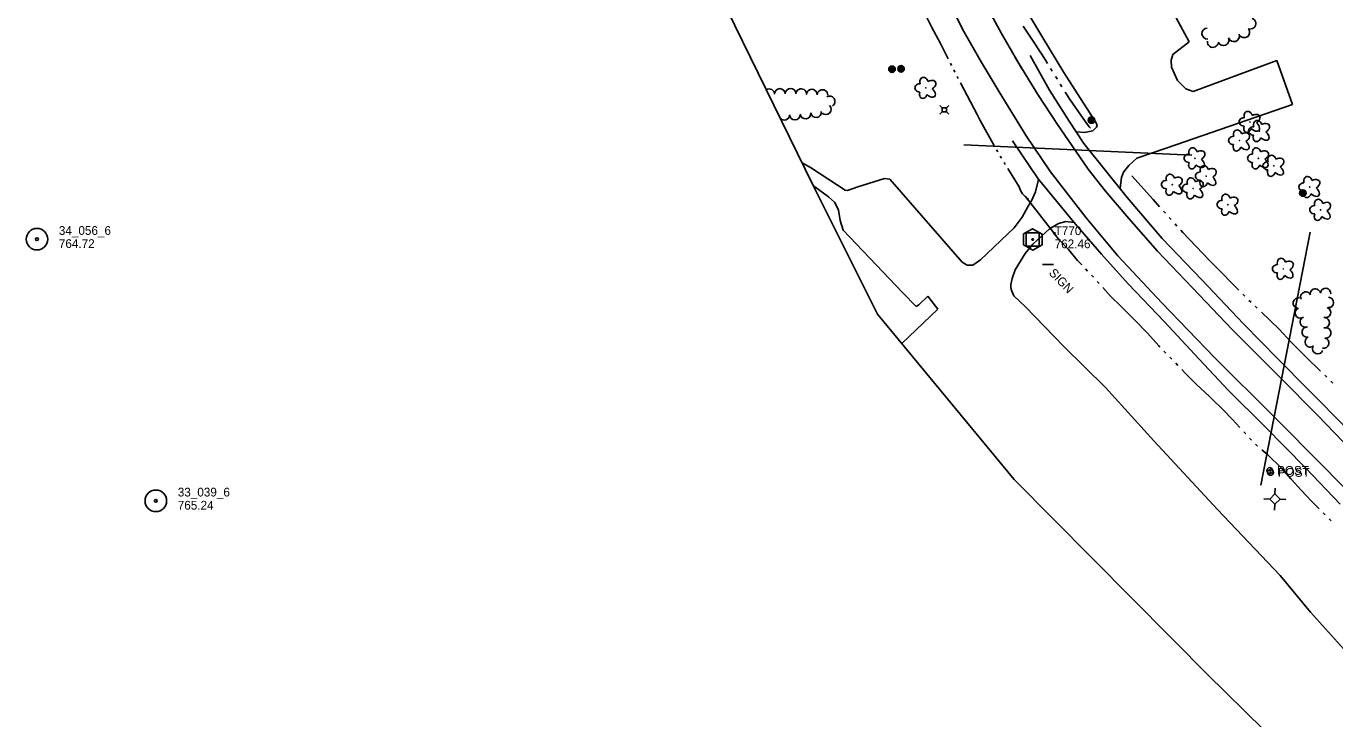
# Model space of a CAD drawing. Extents: x 589250 to 1188077, y 162953 to 363065.
# Drawn here: x 592222 to 593118, y 173959 to 174433 of the extents above; entities that cross this region are included whole.
import ezdxf

# ---------------------------------------------------------------- set-up
doc = ezdxf.new("R2010")
doc.units = 0
for name, color, linetype in [('E_DRN', 7, 'Continuous'), ('E_DRN_DrainTile', 7, 'Continuous'), ('E_DRN_Pipe', 7, 'Continuous'), ('E_DWY', 7, 'Continuous'), ('E_LAND_TreeLine_P', 7, 'Continuous'), ('E_LAND_Vegetation', 7, 'Continuous'), ('E_MAP_Control', 7, 'Continuous'), ('E_MAP_Limits', 7, 'Continuous'), ('E_MAP_PassPoints', 7, 'Continuous'), ('E_MISCPROP', 7, 'Continuous'), ('E_RDWY', 7, 'Continuous'), ('E_RDWY_Gravel', 7, 'Continuous'), ('E_SGN', 7, 'Continuous'), ('E_SGN_Text', 7, 'Continuous'), ('E_UTL_AG_Bold', 7, 'Continuous'), ('E_WTR_FlowLine', 7, 'Continuous')]:
    doc.layers.add(name, color=color, linetype=linetype)

msp = doc.modelspace()

# ---------------------------------------------------------------- linework, layer by layer
at = {"layer": 'E_DRN'}
for centre, radius, start, end in [((592906.93, 174315.61), 0.717, 258.04059, 4.3008), ((592926.09, 174290.91), 0.949, 72.43132, 178.69152)]:
    msp.add_arc(centre, radius, start, end, dxfattribs=at)
at = {"layer": 'E_DRN_DrainTile'}
for p, q in [((593019.9, 174345.12), (592863.65, 174352.13)), ((593100.87, 174292.34), (593067.07, 174118.97))]:
    msp.add_line(p, q, dxfattribs=at)
at = {"layer": 'E_DRN_Pipe'}
msp.add_line((592905.79, 174316.91), (592926.92, 174289.76), dxfattribs=at)
at = {"layer": 'E_DWY'}
for p, q in [((592900.5, 174454.33), (592917.9, 174425.3)), ((593009.02, 174439.01), (593018.06, 174422.58)), ((592917.9, 174425.3), (592932.13, 174401.76)), ((593006.8, 174414.08), (593005.6, 174410.12)), ((593018.06, 174422.58), (593006.8, 174414.08)), ((593005.6, 174410.12), (593005.9, 174405.2)), ((593005.9, 174405.2), (593009.94, 174396.11)), ((593020.86, 174388.58), (593078.1, 174409.86)), ((593078.1, 174409.86), (593088.76, 174379.64)), ((592932.13, 174401.76), (592947.76, 174377.55)), ((593009.94, 174396.11), (593015.66, 174390.5)), ((593015.66, 174390.5), (593020.86, 174388.58)), ((593088.76, 174379.64), (593002.26, 174349.93)), ((592947.76, 174377.55), (592954.41, 174367.16)), ((592941.19, 174360.99), (592940.67, 174361.07)), ((592946.23, 174360.56), (592941.19, 174360.99)), ((592951.97, 174361.7), (592946.23, 174360.56)), ((592954.46, 174364.12), (592951.97, 174361.7)), ((592954.41, 174367.16), (592955.05, 174365.45)), ((592955.05, 174365.45), (592954.46, 174364.12)), ((592982.11, 174343.07), (592976.73, 174337.84)), ((593002.26, 174349.93), (592982.11, 174343.07)), ((592758.76, 174336.56), (592753, 174339.74)), ((592782.34, 174321.11), (592758.76, 174336.56)), ((592973.08, 174333.36), (592971.64, 174329.65)), ((592976.73, 174337.84), (592973.08, 174333.36)), ((592809.48, 174329.15), (592791.21, 174323.34)), ((592812.98, 174328.65), (592809.48, 174329.15)), ((592862.49, 174271.69), (592812.98, 174328.65)), ((592914.91, 174328.38), (592912.88, 174319.84)), ((592971.15, 174326.39), (592970.65, 174322.25)), ((592971.64, 174329.65), (592971.15, 174326.39)), ((592760.75, 174323.92), (592771.02, 174316.56)), ((592771.02, 174316.56), (592775.42, 174312.69)), ((592783.96, 174320.86), (592782.34, 174321.11)), ((592791.21, 174323.34), (592783.96, 174320.86)), ((592912.88, 174319.84), (592909.97, 174313.7)), ((592775.42, 174312.69), (592777.99, 174307.43)), ((592777.99, 174307.43), (592778.97, 174300.31)), ((592907.81, 174310.07), (592903.65, 174302.51)), ((592909.97, 174313.7), (592907.81, 174310.07)), ((592778.97, 174300.31), (592781.1, 174293.66)), ((592903.65, 174302.51), (592898.08, 174295.25)), ((592928.61, 174298.22), (592922.38, 174294.55)), ((592933.61, 174299.68), (592928.61, 174298.22)), ((592939.3, 174298.83), (592933.61, 174299.68)), ((592781.1, 174293.66), (592821.69, 174251.02)), ((592898.08, 174295.25), (592875.14, 174273.42)), ((592916.79, 174289.64), (592911.04, 174284.09)), ((592922.38, 174294.55), (592916.79, 174289.64)), ((592911.04, 174284.09), (592905.62, 174277.62)), ((592866.01, 174269.57), (592862.49, 174271.69)), ((592875.14, 174273.42), (592869.78, 174269.6)), ((592905.62, 174277.62), (592898.8, 174266.54)), ((592869.78, 174269.6), (592866.01, 174269.57)), ((592898.8, 174266.54), (592896.79, 174260.55)), ((592896.79, 174260.55), (592895.9, 174256.4)), ((592895.9, 174256.4), (592895.92, 174254.11)), ((592895.92, 174254.11), (592896.63, 174251.81)), ((592821.69, 174251.02), (592830.97, 174241.44)), ((592832.8, 174242.6), (592839.16, 174248.41)), ((592839.16, 174248.41), (592845.91, 174239.5)), ((592896.63, 174251.81), (592898.04, 174248.61)), ((592898.04, 174248.61), (592905.92, 174241.09)), ((592845.91, 174239.5), (592821.16, 174216.02)), ((592830.97, 174241.44), (592832.8, 174242.6)), ((592905.92, 174241.09), (592932.12, 174213.95)), ((592932.12, 174213.95), (592960.64, 174185.92)), ((592960.64, 174185.92), (592993.88, 174149.36)), ((592993.88, 174149.36), (593037.5, 174102.38)), ((593037.5, 174102.38), (593080.41, 174056.99)), ((593101.04, 174032.06), (593080.41, 174056.99)), ((593152.12, 173975.05), (593101.04, 174032.06))]:
    msp.add_line(p, q, dxfattribs=at)
at = {"layer": 'E_LAND_TreeLine_P'}
for centre, radius, start, end in [((593030.57, 174428.33), 3.79, 92.772, 272.772), ((593059.84, 174435.23), 3.79, 249.19878, 69.19878), ((593034.25, 174422.65), 3.79, 173.44438, 353.44438), ((593041.5, 174423.89), 3.79, 201.88731, 21.88731), ((593048.6, 174426.57), 3.79, 199.34743, 19.34743), ((593055.66, 174429.28), 3.79, 215.78699, 35.78699), ((592730.5, 174386.74), 3.64, 1.65562, 123.29635), ((592737.77, 174386.95), 3.64, 1.65562, 181.65562), ((592745.05, 174387.16), 3.64, 1.65562, 181.65562), ((592752.33, 174386.86), 3.64, 357.41999, 177.41999), ((592759.6, 174386.53), 3.64, 357.41999, 177.41999), ((592766.87, 174386.2), 3.64, 357.41999, 177.41999), ((592769.2, 174376.42), 3.64, 225.48648, 45.48648), ((592771.86, 174381.86), 3.64, 303.2217, 123.2217), ((592733.49, 174372.56), 3.64, 354.12954, 0.98469), ((592740.77, 174372.69), 3.64, 180.98469, 190.41572), ((592740.77, 174372.69), 3.64, 221.76161, 0.98469), ((592748.05, 174372.81), 3.64, 180.98469, 0.98469), ((592755.29, 174373.56), 3.64, 186.96955, 6.96955), ((592762.51, 174374.45), 3.64, 186.96955, 6.96955), ((593104.38, 174249.89), 3.57, 10.03172, 190.03172), ((593111.45, 174250.29), 3.57, 354.22921, 174.22921), ((593092.8, 174243.71), 3.57, 77.57478, 257.57478), ((593097.91, 174247.79), 3.57, 24.53189, 204.53189), ((593113.33, 174244.12), 3.57, 266.75533, 86.75533), ((593094.16, 174236.94), 3.57, 110.00944, 290.00944), ((593111.4, 174237.27), 3.57, 252.13445, 72.13445), ((593097.64, 174230.76), 3.57, 112.37081, 292.37081), ((593098.83, 174223.8), 3.57, 101.87933, 281.87933), ((593110.49, 174230.22), 3.57, 264.85881, 84.85881), ((593111.58, 174223.23), 3.57, 258.68074, 78.68074), ((593100.91, 174217.11), 3.57, 127.97476, 307.97476), ((593110.15, 174216.24), 3.57, 258.04059, 78.04059), ((593106.02, 174212.44), 3.57, 157.94954, 337.94954)]:
    msp.add_arc(centre, radius, start, end, dxfattribs=at)
at = {"layer": 'E_LAND_Vegetation'}
for centre in [(592837.67, 174391.07), (593059.67, 174367.77), (593066.14, 174361.53), (593052.48, 174355.06), (593021.95, 174342.86), (593065.43, 174342.8), (593075.99, 174337.71), (593006.45, 174324.77), (593029.71, 174330.64), (593020.74, 174322.26), (593100.58, 174323.13), (593044.53, 174311.07), (593107.99, 174307.53), (593082.49, 174267.14)]:
    msp.add_circle(centre, 0.128, dxfattribs=at)
for centre, major_axis, ratio in [((592836.45, 174394.78), (0.99, -3.48), 0.782863), ((592840.62, 174393.01), (-3.67, -2.09), 0.691916), ((592833.69, 174391.13), (3.45, -0.05), 0.832022), ((592836.09, 174387.38), (1.23, 3.41), 0.716896), ((592840.3, 174388.5), (-3.54, 3.17), 0.560249), ((593055.68, 174367.84), (3.45, -0.05), 0.832022), ((593058.45, 174371.49), (0.99, -3.48), 0.782863), ((593062.61, 174369.72), (-3.67, -2.09), 0.691916), ((593064.93, 174365.25), (0.99, -3.48), 0.782863), ((593051.26, 174358.78), (0.99, -3.48), 0.782863), ((593055.42, 174357.01), (-3.67, -2.09), 0.691916), ((593058.09, 174364.09), (1.23, 3.41), 0.716896), ((593062.16, 174361.6), (3.45, -0.05), 0.832022), ((593062.3, 174365.21), (-3.54, 3.17), 0.560249), ((593068.78, 174358.97), (-3.54, 3.17), 0.560249), ((593069.09, 174363.48), (-3.67, -2.09), 0.691916), ((593048.49, 174355.13), (3.45, -0.05), 0.832022), ((593050.9, 174351.38), (1.23, 3.41), 0.716896), ((593055.11, 174352.5), (-3.54, 3.17), 0.560249), ((593064.56, 174357.85), (1.23, 3.41), 0.716896), ((593017.97, 174342.92), (3.45, -0.05), 0.832022), ((593020.74, 174346.57), (0.99, -3.48), 0.782863), ((593024.59, 174340.29), (-3.54, 3.17), 0.560249), ((593024.9, 174344.8), (-3.67, -2.09), 0.691916), ((593061.45, 174342.87), (3.45, -0.05), 0.832022), ((593064.21, 174346.52), (0.99, -3.48), 0.782863), ((593068.06, 174340.24), (-3.54, 3.17), 0.560249), ((593068.38, 174344.75), (-3.67, -2.09), 0.691916), ((593074.77, 174341.42), (0.99, -3.48), 0.782863), ((593078.94, 174339.66), (-3.67, -2.09), 0.691916), ((593020.37, 174339.17), (1.23, 3.41), 0.716896), ((593025.72, 174330.7), (3.45, -0.05), 0.832022), ((593028.49, 174334.35), (0.99, -3.48), 0.782863), ((593032.66, 174332.58), (-3.67, -2.09), 0.691916), ((593063.85, 174339.12), (1.23, 3.41), 0.716896), ((593072.01, 174337.78), (3.45, -0.05), 0.832022), ((593074.41, 174334.02), (1.23, 3.41), 0.716896), ((593078.62, 174335.14), (-3.54, 3.17), 0.560249), ((593002.46, 174324.84), (3.45, -0.05), 0.832022), ((593005.23, 174328.48), (0.99, -3.48), 0.782863), ((593009.08, 174322.2), (-3.54, 3.17), 0.560249), ((593009.39, 174326.71), (-3.67, -2.09), 0.691916), ((593016.76, 174322.32), (3.45, -0.05), 0.832022), ((593019.52, 174325.97), (0.99, -3.48), 0.782863), ((593023.69, 174324.2), (-3.67, -2.09), 0.691916), ((593028.13, 174326.95), (1.23, 3.41), 0.716896), ((593032.34, 174328.07), (-3.54, 3.17), 0.560249), ((593096.6, 174323.2), (3.45, -0.05), 0.832022), ((593099.36, 174326.84), (0.99, -3.48), 0.782863), ((593103.53, 174325.08), (-3.67, -2.09), 0.691916), ((593004.87, 174321.08), (1.23, 3.41), 0.716896), ((593019.16, 174318.57), (1.23, 3.41), 0.716896), ((593023.37, 174319.69), (-3.54, 3.17), 0.560249), ((593043.31, 174314.78), (0.99, -3.48), 0.782863), ((593047.48, 174313.01), (-3.67, -2.09), 0.691916), ((593099, 174319.45), (1.23, 3.41), 0.716896), ((593103.21, 174320.56), (-3.54, 3.17), 0.560249), ((593106.78, 174311.24), (0.99, -3.48), 0.782863), ((593040.55, 174311.13), (3.45, -0.05), 0.832022), ((593042.95, 174307.38), (1.23, 3.41), 0.716896), ((593047.16, 174308.5), (-3.54, 3.17), 0.560249), ((593104.01, 174307.6), (3.45, -0.05), 0.832022), ((593110.63, 174304.96), (-3.54, 3.17), 0.560249), ((593110.94, 174309.47), (-3.67, -2.09), 0.691916), ((593106.41, 174303.84), (1.23, 3.41), 0.716896), ((593081.27, 174270.85), (0.99, -3.48), 0.782863), ((593085.44, 174269.08), (-3.67, -2.09), 0.691916), ((593078.51, 174267.2), (3.45, -0.05), 0.832022), ((593080.91, 174263.45), (1.23, 3.41), 0.716896), ((593085.13, 174264.57), (-3.54, 3.17), 0.560249)]:
    msp.add_ellipse(centre, major_axis=major_axis, ratio=ratio, start_param=1.570796, end_param=4.712389, dxfattribs=at)
at = {"layer": 'E_MAP_Control'}
for p, q in [((592906.4, 174282.77), (592906.4, 174291.77)), ((592906.4, 174291.77), (592915.4, 174291.77)), ((592906.4, 174282.77), (592906.4, 174291.77)), ((592906.4, 174291.77), (592915.4, 174291.77)), ((592906.4, 174282.77), (592906.4, 174291.77)), ((592906.4, 174291.77), (592915.4, 174291.77)), ((592915.4, 174291.77), (592915.4, 174282.77)), ((592915.4, 174291.77), (592915.4, 174282.77)), ((592915.4, 174291.77), (592915.4, 174282.77)), ((592915.4, 174282.77), (592906.4, 174282.77)), ((592915.4, 174282.77), (592906.4, 174282.77)), ((592915.4, 174282.77), (592906.4, 174282.77))]:
    msp.add_line(p, q, dxfattribs=at)
msp.add_lwpolyline([(592904.49, 174291.03), (592904.49, 174283.64), (592910.95, 174279.92), (592917.34, 174283.58), (592917.34, 174290.91), (592910.82, 174294.64)], close=True, dxfattribs=at)
msp.add_lwpolyline([(592904.49, 174291.03), (592904.49, 174283.64), (592910.95, 174279.92), (592917.34, 174283.58), (592917.34, 174290.91), (592910.82, 174294.64)], close=True, dxfattribs=at)
msp.add_lwpolyline([(592904.49, 174291.03), (592904.49, 174283.64), (592910.95, 174279.92), (592917.34, 174283.58), (592917.34, 174290.91), (592910.82, 174294.64)], close=True, dxfattribs=at)
msp.add_circle((592910.9, 174287.27), 0.546, dxfattribs=at)
msp.add_circle((592910.9, 174287.27), 0.546, dxfattribs=at)
msp.add_circle((592910.9, 174287.27), 0.546, dxfattribs=at)
at = {"layer": 'E_MAP_Limits'}
for p, q in [((592701.47, 174444.99), (592760.59, 174324.23)), ((592760.59, 174324.23), (592804.66, 174236)), ((592804.66, 174236), (592898.18, 174122.77)), ((592898.18, 174122.77), (593032.42, 173987.52)), ((593339.09, 173685.44), (593030.38, 173989.58))]:
    msp.add_line(p, q, dxfattribs=at)
at = {"layer": 'E_MAP_PassPoints'}
for centre, radius in [((592229.01, 174287.45), 7.38), ((592229.01, 174287.45), 7.38), ((592229.01, 174287.45), 0.945), ((592229.01, 174287.45), 0.945), ((592310.43, 174108.22), 7.38), ((592310.43, 174108.22), 7.38), ((592310.43, 174108.22), 0.945), ((592310.43, 174108.22), 0.945)]:
    msp.add_circle(centre, radius, dxfattribs=at)
at = {"layer": 'E_MISCPROP'}
for centre, radius in [((592814.52, 174403.86), 2.23), ((592814.52, 174403.86), 1.67), ((592814.52, 174403.86), 1.12), ((592820.7, 174404.21), 2.23), ((592820.7, 174404.21), 1.67), ((592820.7, 174404.21), 1.12), ((592820.7, 174404.21), 0.558), ((592814.52, 174403.86), 0.558), ((592951.08, 174369.07), 2.23), ((592951.08, 174369.07), 1.67), ((592951.08, 174369.07), 1.12), ((592951.08, 174369.07), 0.558), ((593095.9, 174319.09), 2.23), ((593095.9, 174319.09), 1.67), ((593095.9, 174319.09), 1.12), ((593095.9, 174319.09), 0.558), ((593073.2, 174129.06), 2), ((593073.69, 174127.71), 2), ((593073.2, 174129.06), 0.25), ((593073.69, 174127.71), 0.25)]:
    msp.add_circle(centre, radius, dxfattribs=at)
at = {"layer": 'E_RDWY'}
for p, q in [((592863.71, 174429.81), (592848.98, 174458.53)), ((592889.44, 174428.46), (592873.56, 174457.75)), ((592875.6, 174408.89), (592863.71, 174429.81)), ((592903.22, 174404.52), (592889.44, 174428.46)), ((592887.92, 174388.5), (592875.6, 174408.89)), ((592898.82, 174411.84), (592914.29, 174386.7)), ((592887.92, 174388.5), (592906.47, 174358.35)), ((592914.29, 174386.7), (592927.78, 174366.05)), ((592927.78, 174366.05), (592937.78, 174351.36)), ((592906.47, 174358.35), (592922.99, 174333.61)), ((592937.78, 174351.36), (592948.87, 174335.4)), ((592922.99, 174333.61), (592947.47, 174302.05)), ((592948.87, 174335.4), (592960.81, 174320.3)), ((592960.81, 174320.3), (592976.64, 174301.6)), ((592947.47, 174302.05), (592969.18, 174276.13)), ((592976.64, 174301.6), (592996.36, 174279.29)), ((592996.36, 174279.29), (593020.28, 174254.03)), ((592969.18, 174276.13), (592999.33, 174243.88)), ((593020.28, 174254.03), (593047.35, 174225.56)), ((592999.33, 174243.88), (593035.46, 174206.51)), ((593047.35, 174225.56), (593079.61, 174193.51)), ((593035.46, 174206.51), (593075.8, 174166.23)), ((593079.61, 174193.51), (593106.24, 174166.35)), ((593075.8, 174166.23), (593110.42, 174131.31)), ((593106.24, 174166.35), (593134.6, 174137.05)), ((593110.42, 174131.31), (593147.29, 174093.46))]:
    msp.add_line(p, q, dxfattribs=at)
at = {"layer": 'E_RDWY_Gravel'}
for p, q in [((592909.11, 174413.22), (592922.48, 174389.5)), ((592922.48, 174389.5), (592935.94, 174368.32)), ((592935.94, 174368.32), (592945.88, 174353.1)), ((592897.11, 174354.93), (592914.54, 174328.83)), ((592945.88, 174353.1), (592975.61, 174316.06)), ((592914.54, 174328.83), (592940.19, 174297.75)), ((592975.61, 174316.06), (592999.63, 174287.84)), ((592940.19, 174297.75), (592958.03, 174277.3)), ((592999.63, 174287.84), (593026.64, 174259.53)), ((592958.03, 174277.3), (592976.18, 174256.86)), ((592976.18, 174256.86), (593001.22, 174230.83)), ((593026.64, 174259.53), (593055.28, 174229.51)), ((593001.22, 174230.83), (593021.6, 174208.8)), ((593055.28, 174229.51), (593078.45, 174205.66)), ((593021.6, 174208.8), (593044.89, 174183.88)), ((593078.45, 174205.66), (593099.52, 174184.56)), ((593044.89, 174183.88), (593069.68, 174159.36)), ((593099.52, 174184.56), (593126.29, 174157.62)), ((593069.68, 174159.36), (593097.96, 174130.61)), ((593097.96, 174130.61), (593121.48, 174105.84))]:
    msp.add_line(p, q, dxfattribs=at)
at = {"layer": 'E_SGN'}
msp.add_line((592917.67, 174270.06), (592925.14, 174270.06), dxfattribs=at)
at = {"layer": 'E_UTL_AG_Bold'}
for p, q in [((593073.17, 174109.47), (593069.17, 174109.56)), ((593076.78, 174112.93), (593073.17, 174109.47)), ((593073.17, 174109.47), (593076.63, 174105.86)), ((593076.63, 174105.86), (593080.24, 174109.32)), ((593076.78, 174112.93), (593076.87, 174116.93)), ((593080.24, 174109.32), (593076.78, 174112.93)), ((593080.24, 174109.32), (593084.24, 174109.24)), ((593076.63, 174105.86), (593076.55, 174101.86))]:
    msp.add_line(p, q, dxfattribs=at)
for points in [[(592848.96, 174377.55), (592847.36, 174379.14)], [(592851.77, 174377.55), (592853.37, 174379.14)], [(592848.96, 174374.74), (592847.36, 174373.14)], [(592851.77, 174374.74), (592853.37, 174373.14)]]:
    msp.add_lwpolyline(points, dxfattribs=at)
msp.add_lwpolyline([(592848.96, 174374.74), (592851.77, 174374.74), (592851.77, 174377.55), (592848.96, 174377.55)], close=True, dxfattribs=at)
at = {"layer": 'E_WTR_FlowLine'}
for p, q in [((592838.09, 174439.75), (592841.91, 174432.56)), ((592841.91, 174432.56), (592847.73, 174421.63)), ((592904.45, 174433.4), (592912.16, 174421.73)), ((592847.73, 174421.63), (592853.07, 174410.95)), ((592912.16, 174421.73), (592919.32, 174410.52)), ((592854.57, 174407.95), (592855.32, 174406.45)), ((592919.32, 174410.52), (592920.95, 174407.89)), ((592856.82, 174403.44), (592856.99, 174403.11)), ((592856.99, 174403.11), (592857.59, 174401.95)), ((592859.15, 174398.98), (592859.92, 174397.49)), ((592923.16, 174404.33), (592924.26, 174402.55)), ((592926.47, 174398.98), (592927.29, 174397.67)), ((592927.29, 174397.67), (592927.57, 174397.2)), ((592861.48, 174394.52), (592865.98, 174385.89)), ((592929.78, 174393.64), (592930.88, 174391.86)), ((592933.09, 174388.29), (592936.44, 174382.87)), ((592865.98, 174385.89), (592872.74, 174372.95)), ((592936.44, 174382.87), (592945.5, 174370.19)), ((592872.74, 174372.95), (592874.97, 174368.67)), ((592945.5, 174370.19), (592949.48, 174364.51)), ((592874.97, 174368.67), (592883.69, 174352.75)), ((592949.48, 174364.51), (592950.51, 174363.42)), ((592883.69, 174352.75), (592884.37, 174351.59)), ((592886.07, 174348.7), (592886.93, 174347.25)), ((592888.63, 174344.36), (592889.48, 174342.92)), ((592891.22, 174340.04), (592892.11, 174338.63)), ((592893.91, 174335.79), (592898.72, 174328.17)), ((592898.72, 174328.17), (592901.49, 174323.39)), ((592978.73, 174330.95), (592993.41, 174314.62)), ((592901.49, 174323.39), (592902.55, 174320.79)), ((592902.55, 174320.79), (592903.87, 174318.6)), ((592903.87, 174318.6), (592907.02, 174315.5)), ((592993.41, 174314.62), (592997.81, 174309.7)), ((593000.44, 174306.77), (593001.75, 174305.3)), ((593004.38, 174302.37), (593005.7, 174300.9)), ((593008.33, 174297.97), (593009.64, 174296.5)), ((592925.74, 174291.02), (592929.27, 174286.88)), ((593012.27, 174293.57), (593013.57, 174292.12)), ((593013.57, 174292.12), (593032.04, 174272.95)), ((592929.27, 174286.88), (592935.31, 174280.35)), ((592935.31, 174280.35), (592941.6, 174272.95)), ((592941.6, 174272.95), (592944.43, 174269.92)), ((593032.04, 174272.95), (593035.57, 174269.29)), ((592947.08, 174267.07), (592948.4, 174265.65)), ((592951.06, 174262.81), (592952.39, 174261.39)), ((593035.57, 174269.29), (593052.02, 174252.54)), ((592955.04, 174258.55), (592956.37, 174257.13)), ((592959, 174254.26), (592964.25, 174248.47)), ((592964.25, 174248.47), (592971.78, 174241.14)), ((593054.78, 174249.73), (593056.16, 174248.33)), ((593058.98, 174245.57), (593060.4, 174244.21)), ((592971.78, 174241.14), (592978.73, 174234.14)), ((593063.23, 174241.47), (593064.65, 174240.1)), ((593067.48, 174237.37), (593079.55, 174225.72)), ((592978.73, 174234.14), (592980.77, 174232.08)), ((592980.77, 174232.08), (592989.39, 174223.09)), ((593079.55, 174225.72), (593087.74, 174217.23)), ((592989.39, 174223.09), (592997.25, 174214.33)), ((593087.74, 174217.23), (593098.06, 174206.54)), ((592997.25, 174214.33), (592997.99, 174213.56)), ((593000.7, 174210.78), (593002.06, 174209.38)), ((593004.77, 174206.6), (593006.13, 174205.2)), ((593008.85, 174202.43), (593010.21, 174201.04)), ((593098.06, 174206.54), (593107.96, 174197.07)), ((593012.93, 174198.26), (593015.61, 174195.53)), ((593015.61, 174195.53), (593023.02, 174187.89)), ((593110.81, 174194.35), (593112.23, 174192.98)), ((593115.08, 174190.26), (593116.5, 174188.9)), ((593023.02, 174187.89), (593031.63, 174179.89)), ((593031.63, 174179.89), (593033.03, 174178.51)), ((593033.03, 174178.51), (593041.18, 174170.46)), ((593041.18, 174170.46), (593047.71, 174163.95)), ((593047.71, 174163.95), (593052.75, 174158.38)), ((593055.38, 174155.52), (593056.71, 174154.1)), ((593059.36, 174151.25), (593060.69, 174149.83)), ((593063.38, 174147.04), (593064.86, 174145.77)), ((593067.81, 174143.24), (593071.97, 174139.68)), ((593071.97, 174139.68), (593081.15, 174130.5)), ((593081.15, 174130.5), (593087.59, 174123.2)), ((593087.59, 174123.2), (593088.01, 174122.73)), ((593088.01, 174122.73), (593094.8, 174115.64)), ((593094.8, 174115.64), (593101.84, 174108.05)), ((593101.84, 174108.05), (593107.08, 174102.84)), ((593109.83, 174100.09), (593111.21, 174098.72)), ((593113.97, 174095.98), (593115.34, 174094.61))]:
    msp.add_line(p, q, dxfattribs=at)

# ---------------------------------------------------------------- texts
at = {"layer": 'E_MAP_Control'}
for s, p in [('T770', (592925.91, 174290.27)), ('T770', (592925.91, 174290.27)), ('T770', (592925.91, 174290.27)), ('762.46', (592925.91, 174281.27)), ('762.46', (592925.91, 174281.27)), ('762.46', (592925.91, 174281.27))]:
    msp.add_text(s, height=6, dxfattribs=at).set_placement(p)
at = {"layer": 'E_MAP_PassPoints'}
for s, p in [('34_056_6', (592244.01, 174290.43)), ('34_056_6', (592244.01, 174290.43)), ('764.72', (592244.01, 174281.43)), ('764.72', (592244.01, 174281.43)), ('33_039_6', (592325.43, 174111.2)), ('33_039_6', (592325.43, 174111.2)), ('765.24', (592325.43, 174102.2)), ('765.24', (592325.43, 174102.2))]:
    msp.add_text(s, height=6, dxfattribs=at).set_placement(p)
at = {"layer": 'E_MISCPROP'}
for p in [(593078.2, 174126.06), (593078.7, 174124.71)]:
    msp.add_text('POST', height=6, dxfattribs=at).set_placement(p)
at = {"layer": 'E_SGN_Text'}
msp.add_text('SIGN', height=6, rotation=313.79094, dxfattribs=at).set_placement((592921.52, 174263.93))

doc.saveas('drawing.dxf')
